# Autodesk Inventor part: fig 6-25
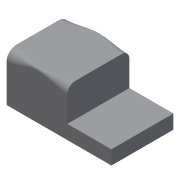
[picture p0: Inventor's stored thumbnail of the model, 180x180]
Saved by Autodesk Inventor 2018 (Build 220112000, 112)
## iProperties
Created: 2004-05
Part Number: fig 6-25
Document SubType Name: Modeling
Designer: CADCIM Technologies
Manufacturer: Standard
Standards Organization: Custom
Density: 1 g/cm^3
Material: Generic
Appearance: Default
Author: CADCIM Technologies
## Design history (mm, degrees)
node "Sketch1"
sketch "Sketch2"
  geometry: L1 (0.098, 47.711)-(0.098, 0.049); L2 (0.098, 0.049)-(-105.483, 0.049); L3 (-105.483, 0.049)-(-105.483, 14.192); L4 (-105.483, 14.192)-(-61.139, 14.192); L5 (-61.139, 14.192)-(-61.139, 47.711); L6 (-61.139, 47.711)-(0.098, 47.711)
  constraints: 12 end point, 3 parallel, 2 perpendicular, 1 vertical
extrude "Extrusion1" new body sketch "Sketch2" stored distance "d0" = 62.5; taper "d1" = 0 deg
fillet "Fillet9" dims "d61" = 10, "d62" = 8, "d63" = 2, "d64" = 5
fillet "Fillet10" dims "d65" = 8, "d66" = 10, "d67" = 2, "d68" = 5
body "Solid1"
